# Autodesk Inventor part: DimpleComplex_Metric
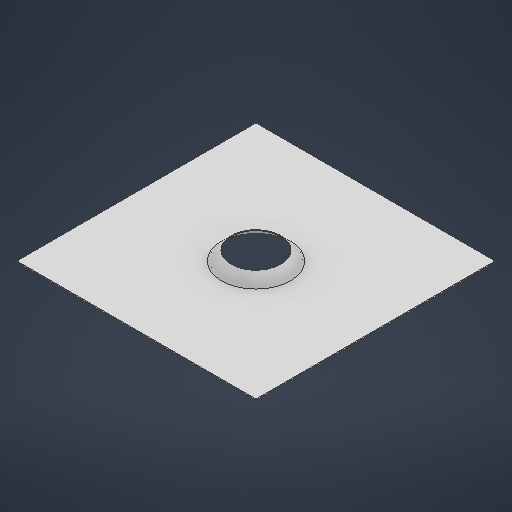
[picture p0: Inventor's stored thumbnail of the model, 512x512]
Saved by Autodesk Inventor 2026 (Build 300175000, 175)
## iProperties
Created: 2025-04
Part Number: DimpleComplex_Metric
Material: Generic
Document SubType Name: Sheet Metal
Designer: Autodesk, Inc
Density: 1 g/cm^3
Sheet Metal Rule: Default_mm
Appearance: Default
Author: Autodesk, Inc
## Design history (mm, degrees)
node "Face1"
  sketch "Sketch1"
    geometry: L1 (-63.5, 63.5)-(63.5, 63.5); L2 (63.5, 63.5)-(63.5, -63.5); L3 (63.5, -63.5)-(-63.5, -63.5); L4 (-63.5, -63.5)-(-63.5, 63.5); L5 (-63.5, 63.5)-(63.5, -63.5); L6 (63.5, 63.5)-(-63.5, -63.5); 1 further point
    constraints: 12 end point, 2 midpoint, 2 parallel, 2 perpendicular, 1 horizontal
    dimensions: "d0" = 127 distance of L1.end L2.end
sketch "Sketch2"
  geometry: C1 r 12.7 at (0, 0); 2 further points
  constraints: 2 coincident, 1 centre point
  dimensions: "Diameter" = 25.4 diameter of C1
extrude "Extrusion1" join sketch "Sketch2" distance "d3" = 5.58 (= Thickness + Height); taper "d4" = 0 deg
workplane "Work Plane1"
sketch "Sketch3"
  geometry: C1 r 12.7 at (0, 0); C2 r 13.2 at (0, 0)
  constraints: 2 centre point, 1 coincident, 1 other
  dimensions: "d6" = 26.4 diameter of C2 (= Diameter + 2 x Thickness); "d7" = 25.4 diameter of C1 (= Diameter)
extrude "Extrusion2" join sketch "Sketch3" distance "d8" = 5.08 (= Height); taper "d9" = 45 deg (= Angle)
extrude "Extrusion3" cut sketch "Sketch3" distance "d10" = 5.58 (= Thickness + Height); taper "d11" = 45 deg (= Angle)
chamfer "Chamfer1" distance "d12" = 0.5 (= Thickness); stored, may be unused: second distance "d13" = 2, angle "d14" = 45 deg (= Angle)
fillet "Fillet1" dims "d15" = 3.302 (= fillet_radius)
body "Solid1"
face "Plate1" dims "d1" = 0.5 (= Thickness)
other parameters: "Thickness" = 0.5, "BendRadius" = 0.5 (= Thickness), "BendReliefWidth" = 0.5 (= Thickness), "BendReliefDepth" = 0.25 (= 0.5 x Thickness), "CornerReliefSize" = 2 (= 4 x Thickness), "SeamGap" = 0.01, "MinimumRemnant" = 1 (= 2 x Thickness), "TransitionRadius" = 0.5 (= BendRadius), "JacobiRadiusSize" = 0.5 (= BendRadius), "GapSize" = 0.5 (= Thickness), "Height" = 5.08 [user parameter; used in 3 equation terms], "Angle" = 45 deg [user parameter; used in 3 equation terms], "fillet_radius" = 3.302 [user parameter; used in 1 equation term], "d5" = -0.5 (= -Thickness)
